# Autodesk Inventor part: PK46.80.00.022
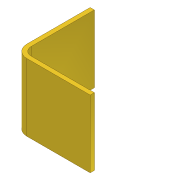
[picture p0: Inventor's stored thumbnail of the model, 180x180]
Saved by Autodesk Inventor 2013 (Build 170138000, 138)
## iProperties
Created: 2005-04
Part Number: PK46.80.00.022
Material: Steel, Mild
Document SubType Name: Sheet Metal
Designer: salex
Manufacturer: Standard
Standards Organization: Custom
Density: 7.86 g/cm^3
Sheet Metal Rule: Default
Mass: 4266.66 g
Surface Area: 1185.52 cm^2
Volume: 542.832 cm^3
Author: salex
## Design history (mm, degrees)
node "ФлнОтгиб1"
body "Solid1"
sketch "Эскиз1"
  geometry: L1 (0, 0)-(0, 170); L2 (0, 0)-(170, 0)
  constraints: 4 end point, 1 perpendicular, 1 vertical, 1 other
  dimensions: "d0" = 170 distance of L1.start L2.end; "d1" = 170 distance of L1.start L1.end (= d0)
feature "Плакирование1" dims "d2" = 160, "d3" = 10 (= BendReliefWidth), "d5" = 20 (= MinimumRemnant), "d7" = 20 (= BendRadius), "d8" = 10, "Thickness" = 10
feature "Изгиб1" dims "d3" = 10 (= BendReliefWidth), "d4" = 5 (= BendReliefDepth), "d5" = 20 (= MinimumRemnant), "d6" = 20 (= BendRadius), "d7" = 20 (= BendRadius), "d8" = 10, "SeamGap" = 0.01, "Thickness" = 10
other parameters: "BendRadius" = 20, "BendReliefDepth" = 5 (= 0.5 x Thickness)
